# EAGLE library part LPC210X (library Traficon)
32bit microcontroller. 128K flash, 64K RAM
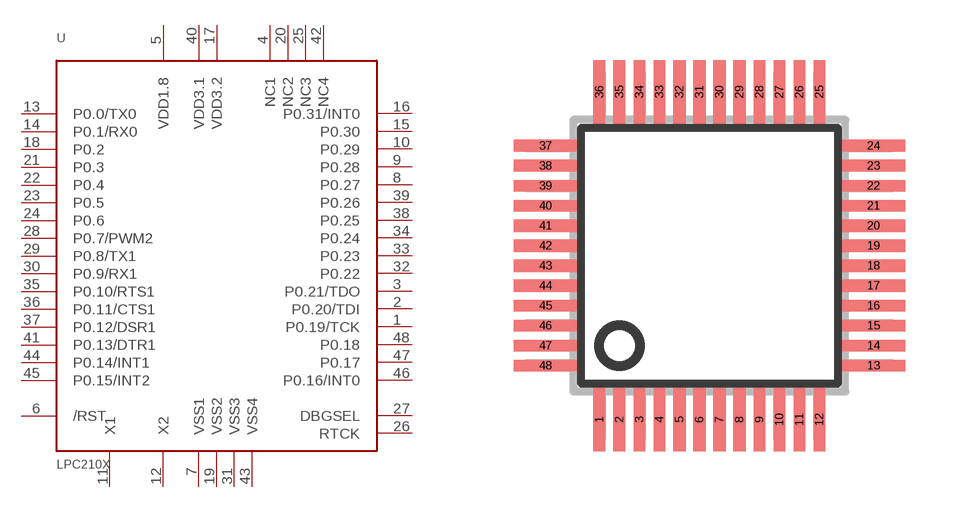
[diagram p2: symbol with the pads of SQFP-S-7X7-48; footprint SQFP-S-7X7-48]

Designator prefix -

## LPC210X  [SQFP-S-7X7-48]
1  P0.19/TCK
2  P0.20/TDI
3  P0.21/TDO
4  NC1  pas
5  VDD1.8  pas
6  /RST  in
7  VSS1  pas
8  P0.27
9  P0.28
10  P0.29
11  X1  in
12  X2  out
13  P0.0/TX0
14  P0.1/RX0
15  P0.30
16  P0.31/INT0
17  VDD3.2  pas
18  P0.2
19  VSS2  pas
20  NC2  pas
21  P0.3
22  P0.4
23  P0.5
24  P0.6
25  NC3  pas
26  RTCK  out
27  DBGSEL  in
28  P0.7/PWM2
29  P0.8/TX1
30  P0.9/RX1
31  VSS3  pas
32  P0.22
33  P0.23
34  P0.24
35  P0.10/RTS1
36  P0.11/CTS1
37  P0.12/DSR1
38  P0.25
39  P0.26
40  VDD3.1  pas
41  P0.13/DTR1
42  NC4  pas
43  VSS4  pas
44  P0.14/INT1
45  P0.15/INT2
46  P0.16/INT0
47  P0.17
48  P0.18

## Footprint SQFP-S-7X7-48 (pad centres in mm)
QFP48 shrink quad flat pack, square
smd 0.3 x 1.6: 1 -2.75,-4.1; 2 -2.25,-4.1; 3 -1.75,-4.1; 4 -1.25,-4.1; 5 -0.75,-4.1; 6 -0.25,-4.1; 7 0.25,-4.1; 8 0.75,-4.1; 9 1.25,-4.1; 10 1.75,-4.1; 11 2.25,-4.1; 12 2.75,-4.1; 25 2.75,4.1; 26 2.25,4.1; 27 1.75,4.1; 28 1.25,4.1; 29 0.75,4.1; 30 0.25,4.1; 31 -0.25,4.1; 32 -0.75,4.1; 33 -1.25,4.1; 34 -1.75,4.1; 35 -2.25,4.1; 36 -2.75,4.1
smd 1.6 x 0.3: 13 4.1,-2.75; 14 4.1,-2.25; 15 4.1,-1.75; 16 4.1,-1.25; 17 4.1,-0.75; 18 4.1,-0.25; 19 4.1,0.25; 20 4.1,0.75; 21 4.1,1.25; 22 4.1,1.75; 23 4.1,2.25; 24 4.1,2.75; 37 -4.1,2.75; 38 -4.1,2.25; 39 -4.1,1.75; 40 -4.1,1.25; 41 -4.1,0.75; 42 -4.1,0.25; 43 -4.1,-0.25; 44 -4.1,-0.75; 45 -4.1,-1.25; 46 -4.1,-1.75; 47 -4.1,-2.25; 48 -4.1,-2.75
